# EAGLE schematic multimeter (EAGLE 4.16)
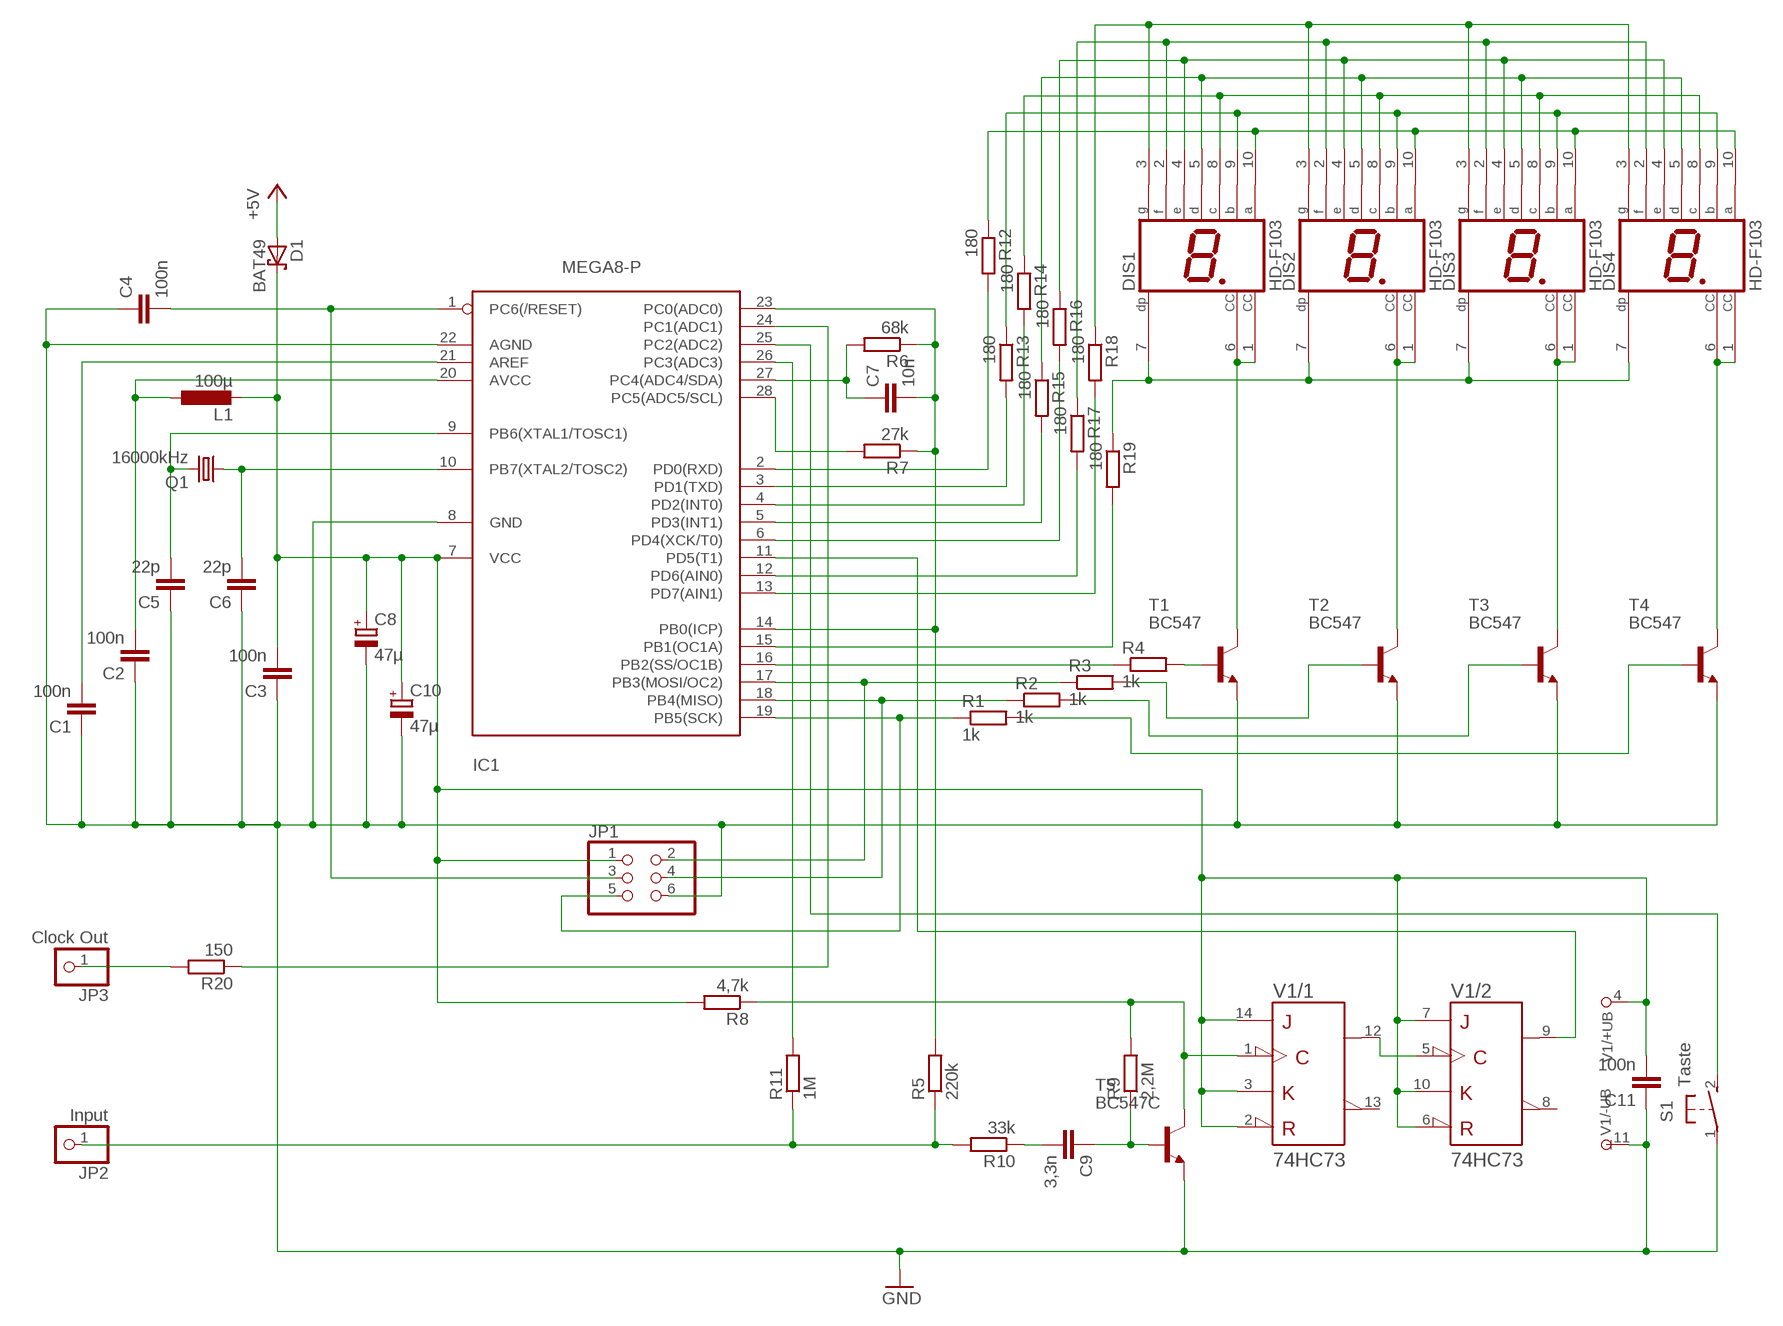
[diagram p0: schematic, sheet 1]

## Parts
C1  100n  C-EU025-030X050  [C025-030X050]
C2  100n  C-EU025-030X050  [C025-030X050]
C3  100n  C-EU025-030X050  [C025-030X050]
C4  100n  C-EU025-030X050  [C025-030X050]
C5  22p  C-EU025-030X050  [C025-030X050]
C6  22p  C-EU025-030X050  [C025-030X050]
C7  10n  C-EU025-030X050  [C025-030X050]
C8  47µ  CPOL-EUE2-5  [E2-5]
C9  3,3n  C-EU025-030X050  [C025-030X050]
C10  47µ  CPOL-EUE2-5  [E2-5]
C11  100n  C-EU025-030X050  [C025-030X050]
D1  BAT49  [DO41-10]
DIS1  HD-F103  [HDSP-E]
DIS2  HD-F103  [HDSP-E]
DIS3  HD-F103  [HDSP-E]
DIS4  HD-F103  [HDSP-E]
IC1  MEGA8-P  [DIL28-3]
JP1  PINHD-2X3  [2X03]
JP2  Input  PINHD-1X1  [1X01]
JP3  Clock Out  PINHD-1X1  [1X01]
L1  100µ  L-EU0207/2V  [0207/2V]
Q1  16000kHz  CRYSTALHC49S  [HC49/S]
R1  1k  R-EU_0207/10  [0207/10]
R2  1k  R-EU_0207/10  [0207/10]
R3  1k  R-EU_0207/10  [0207/10]
R4  1k  R-EU_0207/10  [0207/10]
R5  220k  R-EU_0207/12  [0207/12]
R6  68k  R-EU_0207/12  [0207/12]
R7  27k  R-EU_0207/12  [0207/12]
R8  4,7k  R-EU_0207/12  [0207/12]
R9  2,2M  R-EU_0207/12  [0207/12]
R10  33k  R-EU_0207/12  [0207/12]
R11  1M  R-EU_0207/12  [0207/12]
R12  180  R-EU_0207/12  [0207/12]
R13  180  R-EU_0207/12  [0207/12]
R14  180  R-EU_0207/12  [0207/12]
R15  180  R-EU_0207/12  [0207/12]
R16  180  R-EU_0207/12  [0207/12]
R17  180  R-EU_0207/12  [0207/12]
R18  180  R-EU_0207/12  [0207/12]
R19  180  R-EU_0207/12  [0207/12]
R20  150  R-EU_0207/12  [0207/12]
S1  Taste  31-XX  [B3F-31XX]
T1  BC547  [TO92]
T2  BC547  [TO92]
T3  BC547  [TO92]
T4  BC547  [TO92]
T5  BC547C  BC547  [TO92]
V1  74HC73  7473N  [DIL14]

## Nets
+5V: D1.A
GND: C1.1 C2.1 C3.1 C4.1 C5.1 C6.1 C8.- C10.- C11.1 IC1.8(GND) IC1.22(AGND) JP1.6 S1.1(P) T1.1(E) T2.1(E) T3.1(E) T4.1(E) T5.1(E) V1.11(/-UB:-UB)
N$1: C4.2 IC1.1(PC6(/RESET)) JP1.3
N$2: C1.2 IC1.21(AREF)
N$3: C2.2 IC1.20(AVCC) L1.1
N$4: IC1.3(PD1(TXD)) R13.2
N$5: C5.2 IC1.9(PB6(XTAL1/TOSC1)) Q1.2
N$6: C6.2 IC1.10(PB7(XTAL2/TOSC2)) Q1.1
N$7: IC1.4(PD2(INT0)) R14.2
N$8: DIS1.10(A) DIS2.10(A) DIS3.10(A) DIS4.10(A) R12.1
N$9: DIS1.9(B) DIS2.9(B) DIS3.9(B) DIS4.9(B) R13.1
N$10: DIS1.8(C) DIS2.8(C) DIS3.8(C) DIS4.8(C) R14.1
N$11: DIS1.5(D) DIS2.5(D) DIS3.5(D) DIS4.5(D) R15.1
N$12: DIS1.4(E) DIS2.4(E) DIS3.4(E) DIS4.4(E) R16.1
N$13: DIS1.3(G) DIS2.3(G) DIS3.3(G) DIS4.3(G) R18.1
N$14: DIS1.2(F) DIS2.2(F) DIS3.2(F) DIS4.2(F) R17.1
N$15: DIS1.7(DP) DIS2.7(DP) DIS3.7(DP) DIS4.7(DP) R19.1
N$16: DIS1.1(CC) DIS1.6(CC) T1.3(C)
N$17: DIS2.1(CC) DIS2.6(CC) T2.3(C)
N$18: DIS3.1(CC) DIS3.6(CC) T3.3(C)
N$19: DIS4.1(CC) DIS4.6(CC) T4.3(C)
N$20: IC1.19(PB5(SCK)) JP1.5 R1.1
N$21: IC1.5(PD3(INT1)) R15.2
N$22: IC1.2(PD0(RXD)) R12.2
N$23: IC1.6(PD4(XCK/T0)) R16.2
N$24: IC1.12(PD6(AIN0)) R17.2
N$25: IC1.13(PD7(AIN1)) R18.2
N$26: IC1.15(PB1(OC1A)) R19.2
N$27: IC1.18(PB4(MISO)) JP1.4 R2.1
N$28: IC1.17(PB3(MOSI/OC2)) JP1.2 R3.1
N$29: IC1.16(PB2(SS/OC1B)) R4.1
N$30: R4.2 T1.2(B)
N$31: R3.2 T2.2(B)
N$32: R2.2 T3.2(B)
N$33: R1.2 T4.2(B)
N$34: C7.1 IC1.27(PC4(ADC4/SDA)) R6.2
N$35: C9.2 R10.1
N$36: JP2.1 R5.1 R10.2 R11.1
N$37: IC1.25(PC2(ADC2)) S1.2(S)
N$38: IC1.28(PC5(ADC5/SCL)) R7.2
N$39: C7.2 IC1.14(PB0(ICP)) IC1.23(PC0(ADC0)) R5.2 R6.1 R7.1
N$40: R8.1 R9.2 T5.3(C) V1.1(/1:CLK)
N$41: IC1.11(PD5(T1)) V1.9(/2:Q)
N$42: C9.1 R9.1 T5.2(B)
N$43: V1.5(/2:CLK) V1.12(/1:Q)
N$44: IC1.26(PC3(ADC3)) R11.2
N$45: C3.2 C8.+ C10.+ C11.2 D1.C IC1.7(VCC) JP1.1 L1.2 R8.2 V1.2(/1:CLR\) V1.3(/1:K) V1.4(/+UB:+UB) V1.6(/2:CLR\) V1.7(/2:J) V1.10(/2:K) V1.14(/1:J)
N$46: JP3.1 R20.2
N$47: IC1.24(PC1(ADC1)) R20.1
Unconnected: V1.8(/2:Q\) V1.13(/1:Q\)

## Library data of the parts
C1-C7 C9 C11 = rcl:C-EU: CAPACITOR, European symbol
C8 C10 = rcl:CPOL-EU: POLARIZED CAPACITOR, European symbol
D1 = diode:BAT49: DIODE
DIS1-DIS4 = display-hp:HD-F103: LED DISPLAY 1-character 7 segment, decimal point right
IC1 = atmel:MEGA8-P: MICROCONTROLLER 8 Kbytes FLASH 1 kbytes SRAM 512 bytes EEPROM USART 4-channel 10 bit ADC 2-channel 8 bit ADC Source: avr.lbr
JP1 = pinhead:PINHD-2X3: PIN HEADER
JP2 JP3 = pinhead:PINHD-1X1: PIN HEADER
L1 = rcl:L-EU: INDUCTOR, European symbol
Q1 = crystal:CRYSTAL: CRYSTAL
R1-R20 = rcl:R-EU_: RESISTOR, European symbol
S1 = switch-omron:31-XX: OMRON SWITCH
T1-T5 = transistor:BC547: NPN TRANSISTOR
V1 = 74ttl-din:74*73: Dual J-K FLIP FLOP, clear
